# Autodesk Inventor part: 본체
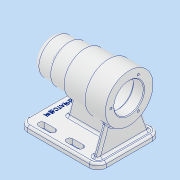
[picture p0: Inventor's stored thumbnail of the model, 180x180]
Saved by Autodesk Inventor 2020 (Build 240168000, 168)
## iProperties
Created: 2021-10
Part Number: 본체
Material: 알루미늄 6061
Document SubType Name: Modeling
Designer: user
Density: 2.7 g/cm^3
Appearance: 알루미늄 - 평지
Mass: 690.248 g
Surface Area: 701.718 cm^2
Volume: 255.647 cm^3
Author: user
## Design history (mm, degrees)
sketch "스케치1"
  geometry: L1 (-56, 0)-(56, 0); L2 (-56, 25)-(-32, 25); L3 (-56, 0)-(-56, 25); L4 (-32, 25)-(-32, 27); L5 (-32, 27)-(-10, 27); L6 (-10, 27)-(-10, 30); L7 (-10, 30)-(24, 30); L8 (24, 30)-(24, 34); L9 (24, 34)-(56, 34); L10 (56, 34)-(56, 21); L11 (56, 21)-(41, 21); L12 (41, 21)-(41, 24); L13 (41, 24)-(-13, 24); L14 (-13, 24)-(-13, 21); L15 (-13, 21)-(-25, 21); L16 (-25, 21)-(-25, 17.5); L17 (-25, 17.5)-(-43, 17.5); L18 (-43, 17.5)-(-43, 16); L19 (-43, 16)-(-47, 16); L20 (-47, 16)-(-47, 10.5); L21 (-47, 10.5)-(-50, 10.5); L22 (-50, 10.5)-(-50, 0); L23 (-56, 0)-(-50, 0); 3 further points
  constraints: 46 end point, 16 perpendicular, 3 horizontal, 3 vertical, 1 coincident, 1 midpoint
  dimensions: "d0" = 112 distance of L1.start L1.end; "d1" = 21 diameter of L21 L1; "d2" = 32 diameter of L19 L1; "d3" = 35 diameter of L17 L1; "d4" = 42 diameter of L15 L1; "d5" = 48 diameter of L13 L1; "d6" = 42 diameter of L11 L1; "d7" = 50 diameter of L2 L1; "d8" = 54 diameter of L5 L1; "d9" = 60 diameter of L7 L1; "d10" = 68 diameter of L9 L1; "d11" = 24 distance between parallel lines of L4 L3; "d12" = 46 distance between parallel lines of L6 L3; "d13" = 80 distance between parallel lines of L8 L3; "d14" = 112 distance between parallel lines of L10 L3; "d15" = 3 distance between parallel lines of L20 L22; "d16" = 4 distance between parallel lines of L18 L20; "d17" = 18 distance between parallel lines of L16 L18; "d19" = 12 distance between parallel lines of L14 L16; "d20" = 54 distance between parallel lines of L12 L14; "d21" = 15 distance between parallel lines of L10 L12
revolve "회전1" sketch "스케치1" stored, may be unused: angle "d22" = 90 deg
node "작업 평면1"
sketch "스케치2"
  geometry: L1 (56, 25)-(56, -25) reference; L2 (56, 0)-(56, -45); L3 (56, -45)-(-56, -45); L4 (-56, -45)-(-56, 45); L5 (-56, 45)-(56, 45); L6 (56, 45)-(56, 0); 3 further points
  constraints: 10 end point, 2 collinear, 2 perpendicular, 1 midpoint, 1 vertical
  dimensions: "d24" = 45 distance of L2.start L2.end; "d25" = 112 distance of L2.end L3.end; "d26" = 90 distance of L3.end L4.end
extrude "돌출1" join sketch "스케치2" distance "d27" = 8; taper "d28" = 0 deg
fillet "모깎기1" dims "d29" = 12
node "작업 평면2"
sketch "스케치5"
  geometry: L1 (-24.658, 23.409)-(-62, 37); L2 (-24.658, -23.409)-(-62, -37); L3 (-62, 45)-(-62, 33) reference; L4 (-62, -33)-(-62, -45) reference; L5 (-62, 45)-(-70, 45) reference; L6 (-70, -45)-(-62, -45) reference; L7 (-62, 44.314)-(-62, -44.314) reference; L8 (-62, -44.314)-(-70, -44.314) reference; L9 (-70, -44.314)-(-70, 44.314) reference; L10 (-70, 44.314)-(-62, 44.314) reference; C1 r 21 at (0, 0) reference; A1 r 34 centre (0, 0) between (-24.658, 23.409) and (-24.658, -23.409) reference; A2 r 34 centre (0, 0) between (-24.658, 23.409) and (-24.658, -23.409) reference; 1 further point
  constraints: 4 end point, 2 point on circle, 2 point on line
  dimensions: "d31" = 8 distance from line of L5 L1.end; "d32" = 8 distance from line of L6 L2.end; "d33" = 110 deg angle of L3 L1; "d34" = 110 deg angle of L4 L2
extrude "돌출2" join sketch "스케치5" distance "d35" = 8; taper "d36" = 0 deg
node "작업 평면3"
sketch "스케치10"
  geometry: L1 (48, -24.658)-(48, -62) reference; L2 (-44, -62)-(44, -62) reference; L3 (-19.622, -27)-(-29, -62); 1 further point
  constraints: 2 end point, 1 point on line
  dimensions: "d40" = 105 deg angle of L2 L3; "d41" = 77 distance from line of L1 L3.end
feature "리브1" sketch "스케치10" dims "d42" = 1, "d43" = 8, "d44" = 0, "d45" = 0, "d46" = 1, "d47" = 1
sketch "스케치11"
  geometry: L1 (-36, -33)-(-21, -33); L2 (-36, -37.5)-(-21, -37.5); L3 (-21, -28.5)-(-36, -28.5); L4 (-56, 33)-(-56, -33) reference; L5 (40, 37)-(48, 37) reference; L6 (48, 37)-(48, -37) reference; L7 (48, -37)-(40, -37) reference; L8 (40, -37)-(40, -4) reference; L9 (40, -4)-(-29, -4) reference; L10 (-29, -4)-(-29, 4) reference; L11 (-29, 4)-(40, 4) reference; L12 (40, 4)-(40, 37) reference; L13 (-44, 45)-(44, 45) reference; L14 (56, 33)-(56, -33) reference; L15 (44, -45)-(-44, -45) reference; L16 (-56, -33)-(-56, 33) reference; L17 (40, -37)-(40, -4) reference; L18 (40, -4)-(-29, -4) reference; L19 (-29, -4)-(-29, 4) reference; L20 (-29, 4)-(40, 4) reference; L21 (40, 4)-(40, 37) reference; L22 (-44, 45)-(44, 45) reference; L23 (56, 33)-(56, -33) reference; L24 (44, -45)-(-44, -45) reference; L25 (-56, -33)-(-56, 33) reference; L26 (4, -33)-(19, -33); L27 (4, -37.5)-(19, -37.5); L28 (19, -28.5)-(4, -28.5); L29 (-36, 33)-(-21, 33); L30 (-36, 28.5)-(-21, 28.5); L31 (-21, 37.5)-(-36, 37.5); L32 (4, 33)-(19, 33); L33 (44, 45)-(-44, 45) reference; L34 (4, 28.5)-(19, 28.5); L35 (19, 37.5)-(4, 37.5); L36 (40, 37)-(48, 37) reference; L37 (48, 37)-(48, -37) reference; L38 (48, -37)-(40, -37) reference; A1 r 4.5 centre (-36, -33) between (-36, -28.5) and (-36, -37.5); A2 r 4.5 centre (-21, -33) between (-21, -37.5) and (-21, -28.5); A3 r 12 centre (-44, 33) between (-44, 45) and (-56, 33) reference; A4 r 12 centre (44, 33) between (56, 33) and (44, 45) reference; A5 r 12 centre (44, -33) between (44, -45) and (56, -33) reference; A6 r 12 centre (-44, -33) between (-56, -33) and (-44, -45) reference; A7 r 12 centre (-44, 33) between (-44, 45) and (-56, 33) reference; A8 r 12 centre (44, 33) between (56, 33) and (44, 45) reference; A9 r 12 centre (44, -33) between (44, -45) and (56, -33) reference; A10 r 12 centre (-44, -33) between (-56, -33) and (-44, -45) reference; A11 r 4.5 centre (4, -33) between (4, -28.5) and (4, -37.5); A12 r 4.5 centre (19, -33) between (19, -37.5) and (19, -28.5); A13 r 4.5 centre (-36, 33) between (-36, 37.5) and (-36, 28.5); A14 r 4.5 centre (-21, 33) between (-21, 28.5) and (-21, 37.5); A15 r 4.5 centre (4, 33) between (4, 37.5) and (4, 28.5); A16 r 4.5 centre (19, 33) between (19, 28.5) and (19, 37.5); 5 further points
  constraints: 32 end point, 16 point on circle, 16 tangent, 8 centre point, 5 parallel, 4 midpoint, 2 horizontal, 2 point on line
  dimensions: "d48" = 9 diameter of A2; "d49" = 20 distance from line of L4 L1.start; "d50" = 33 vertical distance of point (0, 0) point (-28.5, -33); "d51" = 15 distance of L3.start L3.end; "d52" = 15 distance of L26.start L26.end; "d53" = 9 diameter of A12; "d54" = 60 distance from line of L4 L26.start; "d55" = 15 distance of L29.start L29.end; "d56" = 9 diameter of A14; "d57" = 20 distance from line of L4 L29.start; "d58" = 33 vertical distance of point (0, 0) L29.start; "d59" = 33 vertical distance of point (0, 0) point (11.5, 33); "d60" = 60 distance from line of L4 L32.start; "d61" = 4.5 radius of A16; "d62" = 67.5 distance from line of L4 point (11.5, 33)
extrude "돌출3" cut sketch "스케치11" distance "d63" = 93.25; taper "d64" = 0 deg
sketch "스케치13"
  geometry: 2 further points
  constraints: 1 horizontal alignment
  dimensions: "d65" = 26 distance of point (0, 0) point (-26, 0)
hole "구멍1" sketch "스케치13" at (-26, 0) diameter "d66" = 3.242; stored, may be unused: countersink angle "d70" = 90 deg, drill point angle "d72" = 118 deg; dims "d67" = 8, "d68" = 4, "d69" = 2, "d71" = 11
fillet "모깎기2" dims "d76" = 0.3
fillet "모깎기4" dims "d78" = 3
fillet "모깎기5" dims "d79" = 8
fillet "모깎기6" dims "d80" = 3
chamfer "모따기1" distance "d81" = 1; stored, may be unused: second distance "d82" = 2, angle "d83" = 45 deg
fillet "모깎기7" dims "d84" = 3
fillet "모깎기8" dims "d85" = 3
sketch "스케치14"
  geometry: L1 (-25.09, -7)-(37, -7) reference; L2 (37, -7)-(37, -32.716) reference; L3 (51, -32.716)-(51, 32.716) reference; L4 (37, 32.716)-(37, 7) reference; L5 (37, 7)-(-25.09, 7) reference; L6 (-31.302, 1)-(-31.302, -1) reference; L7 (-44, -42)-(44, -42) reference; L8 (-53, 33)-(-53, -33) reference; L9 (44, 42)-(-44, 42) reference; L10 (53, -33)-(53, 33) reference; L11 (-36, 28.5)-(-21, 28.5) reference; L12 (-21, 37.5)-(-36, 37.5) reference; L13 (4, -37.5)-(19, -37.5) reference; L14 (19, -28.5)-(4, -28.5) reference; L15 (19, 37.5)-(4, 37.5) reference; L16 (4, 28.5)-(19, 28.5) reference; L17 (-36, -37.5)-(-21, -37.5) reference; L18 (-21, -28.5)-(-36, -28.5) reference; L19 (-56, 33)-(-56, -33) reference; L20 (43, -39.101)-(45, -39.101) reference; L21 (45, 39.101)-(43, 39.101) reference; A1 r 9 centre (-44, -33) between (-53, -33) and (-44, -42) reference; A2 r 9 centre (-44, 33) between (-44, 42) and (-53, 33) reference; A3 r 9 centre (44, -33) between (44, -42) and (53, -33) reference; A4 r 9 centre (44, 33) between (53, 33) and (44, 42) reference; A5 r 4.5 centre (-21, 33) between (-21, 28.5) and (-21, 37.5) reference; A6 r 4.5 centre (-36, 33) between (-36, 37.5) and (-36, 28.5) reference; A7 r 4.5 centre (4, -33) between (4, -28.5) and (4, -37.5) reference; A8 r 4.5 centre (19, -33) between (19, -37.5) and (19, -28.5) reference; A9 r 4.5 centre (19, 33) between (19, 28.5) and (19, 37.5) reference; A10 r 4.5 centre (4, 33) between (4, 37.5) and (4, 28.5) reference; A11 r 4.5 centre (-21, -33) between (-21, -37.5) and (-21, -28.5) reference; A12 r 4.5 centre (-36, -33) between (-36, -28.5) and (-36, -37.5) reference; 2 further points
  constraints: 1 horizontal alignment, 7 other
  dimensions: "d86" = 12 distance from line of L19 point (-44, 0)
feature "엠보싱1" sketch "스케치14" dims "d16" = 4, "d87" = 0.5, "d88" = 0
fillet "모깎기9" dims "d89" = 3
fillet "모깎기10" dims "d90" = 3
node "솔리드1"
pattern_circular "원형 패턴1" dims angle "d74" = 360 deg
node "절단 모서리 투영1"
node "절단 모서리 투영4"
node "절단 모서리 투영5"
node "절단 모서리 투영6"
feature "A9D066F2-1C7D-4E18-AEED-F7BC21143FA4" dims "d66" = 3.242, "d67" = 8, "d68" = 4, "d69" = 2, "d70" = 90 deg, "d71" = 11, "d72" = 118 deg
other parameters: "d30" = 48, "d37" = 0
